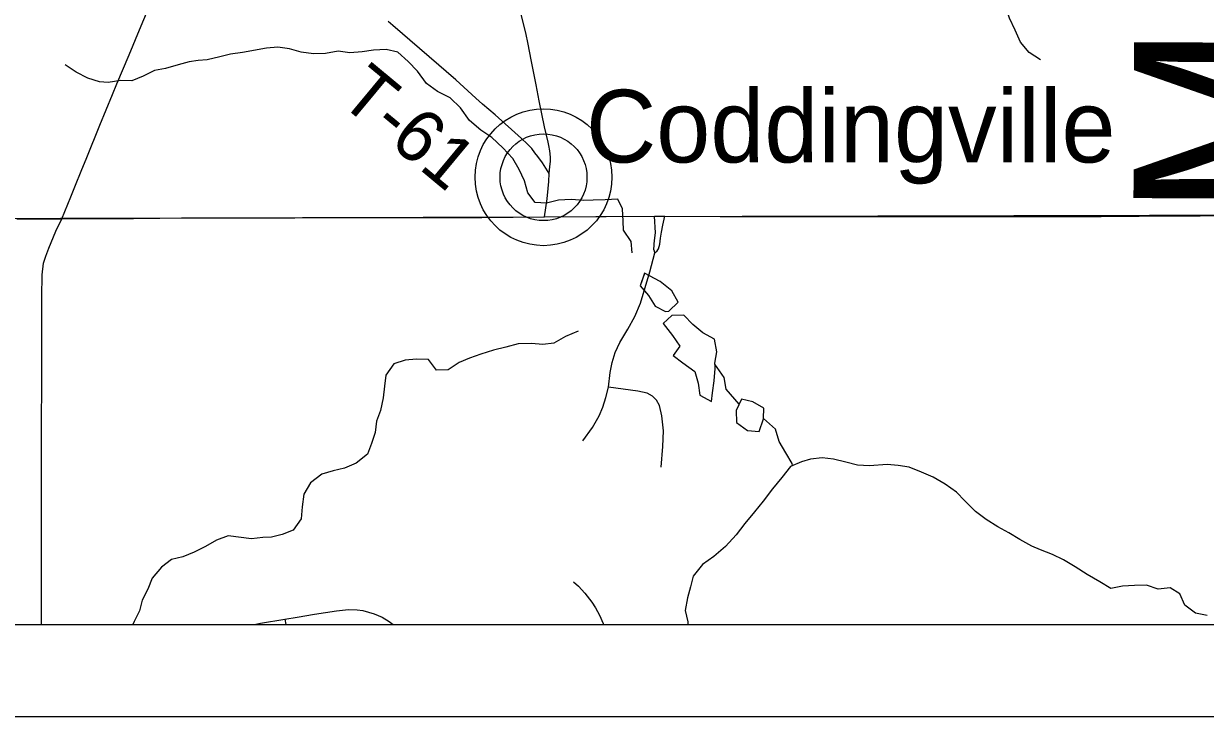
# Model space of a CAD drawing. Extents: x 0 to 34, y 0 to 22.
# Drawn here: x 6.454 to 7.738, y 14 to 14.753 of the extents above; entities that cross this region are included whole.
import ezdxf

# ---------------------------------------------------------------- set-up
doc = ezdxf.new("R2010")
doc.units = 0
for name, color, linetype in [('GM_X_Corporation', 7, 'Continuous'), ('GM_X_County_Text', 7, 'Continuous'), ('GM_X_Minor_Lake', 7, 'Continuous'), ('GM_X_Minor_River', 7, 'Continuous'), ('GM_X_State_Route', 7, 'Continuous'), ('GM_X_Township_Road', 7, 'Continuous'), ('GM_X_Township_Road_Text', 7, 'Continuous'), ('GM_X_Unincorporated', 7, 'Continuous'), ('GM_X_Unincorporated_Location', 7, 'Continuous'), ('GM_X_Unincorporated_Text', 7, 'Continuous'), ('SH_Data', 7, 'Continuous')]:
    doc.layers.add(name, color=color, linetype=linetype)

msp = doc.modelspace()

# ---------------------------------------------------------------- linework, layer by layer
at = {"layer": 'GM_X_Corporation'}
for points in [[(2.1, 20.9), (2.1, 14.1), (7.9734, 14.1), (7.9726, 14.5453), (7.9765, 15.2637), (7.9792, 15.5481), (7.979, 15.5988), (7.9808, 15.7192), (7.9807, 15.9078), (7.9821, 16.2487), (7.9825, 16.3395), (7.9818, 16.3982), (7.9825, 16.6077), (7.9838, 16.7968), (7.9877, 17.3871), (7.9891, 17.5498), (7.991, 17.7727), (7.9901, 18.1613)], [(7.9901, 18.1613), (7.991, 17.7727), (7.9891, 17.5498), (7.9877, 17.3871), (7.9838, 16.7968), (7.9825, 16.6077), (7.9818, 16.3982), (7.9825, 16.3395), (7.9821, 16.2487), (7.9807, 15.9078), (7.9808, 15.7192), (7.979, 15.5988), (7.9792, 15.5481), (7.9765, 15.2637), (7.9726, 14.5453), (7.0871, 14.5429), (7.0197, 14.5427), (6.4941, 14.5412), (6.1476, 14.5397), (5.4644, 14.5374), (4.5212, 14.531)]]:
    msp.add_lwpolyline(points, dxfattribs=at)
msp.add_lwpolyline([(2.8649, 14.1), (7.9734, 14.1), (7.9726, 14.5453), (7.0871, 14.5429), (7.0197, 14.5427), (6.4941, 14.5412), (6.1476, 14.5397), (5.4644, 14.5374), (4.5212, 14.531), (4.3772, 14.5296), (4.3422, 14.5307), (3.735, 14.5275), (3.3839, 14.5264), (3.3511, 14.525), (2.8655, 14.5214), (2.8638, 14.4461)], close=True, dxfattribs=at)
at = {"layer": 'GM_X_Minor_Lake'}
for points in [[(7.1289, 14.4817), (7.1239, 14.4682), (7.1331, 14.4576), (7.1404, 14.4458), (7.1514, 14.4402)], [(7.1288, 14.4816), (7.1239, 14.4682), (7.1331, 14.4576), (7.1404, 14.4458), (7.1514, 14.4402)], [(7.1514, 14.4402), (7.1552, 14.4406), (7.1654, 14.4502), (7.1585, 14.4627), (7.1459, 14.4729), (7.1289, 14.4817)], [(7.1514, 14.4402), (7.1552, 14.4406), (7.1654, 14.4502), (7.1585, 14.4627), (7.1459, 14.4729), (7.1289, 14.4817)], [(7.2054, 14.3815), (7.2053, 14.3839), (7.2072, 14.3964), (7.2049, 14.4101), (7.192, 14.4169), (7.1813, 14.4261), (7.1714, 14.4363), (7.1584, 14.4359), (7.1489, 14.4272), (7.1592, 14.4142)], [(7.1592, 14.4142), (7.1672, 14.4025), (7.16, 14.3922), (7.1703, 14.3842), (7.1833, 14.3751), (7.1871, 14.3622), (7.189, 14.3492), (7.2016, 14.3424), (7.2027, 14.3519), (7.2046, 14.3649), (7.2055, 14.3782), (7.2054, 14.3815)], [(7.1592, 14.4142), (7.1672, 14.4025), (7.16, 14.3922), (7.1703, 14.3842), (7.1833, 14.3751), (7.1871, 14.3622), (7.189, 14.3492), (7.2016, 14.3424), (7.2027, 14.3519), (7.2046, 14.3649), (7.2055, 14.3782), (7.2054, 14.3816)], [(7.2579, 14.3234), (7.2579, 14.3237), (7.2583, 14.3349), (7.2465, 14.3421), (7.2343, 14.3447), (7.2282, 14.3326)], [(7.2579, 14.3235), (7.2579, 14.3237), (7.2583, 14.3349), (7.2465, 14.3421), (7.2343, 14.3447), (7.2282, 14.3326)], [(7.2282, 14.3326), (7.2286, 14.3193), (7.2408, 14.3109), (7.2534, 14.3098), (7.2579, 14.3234)], [(7.2282, 14.3326), (7.2286, 14.3193), (7.2408, 14.3109), (7.2534, 14.3098), (7.2579, 14.3235)]]:
    msp.add_lwpolyline(points, dxfattribs=at)
at = {"layer": 'GM_X_Minor_River'}
for points in [[(7.5591, 14.7137), (7.5469, 14.7216), (7.5374, 14.733), (7.5316, 14.746), (7.5255, 14.7589), (7.5213, 14.7718), (7.5179, 14.7847), (7.5148, 14.798), (7.5121, 14.8102), (7.5053, 14.822), (7.5011, 14.8349), (7.4992, 14.8486), (7.4904, 14.8581), (7.4774, 14.8577)], [(7.1154, 14.5039), (7.1142, 14.5161), (7.1058, 14.5286), (7.1054, 14.5385), (7.105, 14.5518), (7.0997, 14.5621), (7.086, 14.5617), (7.073, 14.5613), (7.0628, 14.5609), (7.0491, 14.562), (7.0354, 14.5613), (7.0224, 14.5578), (7.0099, 14.5586), (7.0019, 14.5692), (6.9984, 14.5821), (6.9927, 14.5947), (6.9855, 14.6065), (6.9748, 14.6182), (6.963, 14.6292), (6.9508, 14.6372), (6.9386, 14.6479), (6.9287, 14.6615), (6.9176, 14.6725), (6.9039, 14.6794), (6.8917, 14.6881), (6.8822, 14.7014), (6.8719, 14.712), (6.8605, 14.7219), (6.8479, 14.7249), (6.8342, 14.7242), (6.8221, 14.7223), (6.8084, 14.7215), (6.7958, 14.723), (6.7821, 14.7207), (6.7692, 14.7203), (6.7555, 14.7222), (6.7429, 14.7256), (6.7304, 14.7275), (6.7178, 14.7263), (6.6919, 14.7217), (6.679, 14.7198), (6.6672, 14.7171), (6.6535, 14.7137), (6.6436, 14.7129), (6.6341, 14.7114), (6.622, 14.7083), (6.6083, 14.7045), (6.5961, 14.7022), (6.5839, 14.6961), (6.5718, 14.6908), (6.5596, 14.6911), (6.5459, 14.6892), (6.5364, 14.6899), (6.5238, 14.6937), (6.5112, 14.7002), (6.4991, 14.7082)], [(7.0565, 14.4187), (7.0428, 14.413), (7.0303, 14.4057), (7.0181, 14.4042), (7.0059, 14.4053), (6.9915, 14.4049), (6.9781, 14.4015), (6.9645, 14.398), (6.9508, 14.3938), (6.9386, 14.3896), (6.9272, 14.3847), (6.9154, 14.3767), (6.9028, 14.3763), (6.8941, 14.3881), (6.8811, 14.3884), (6.8686, 14.3873), (6.8564, 14.3834), (6.8477, 14.3709), (6.8462, 14.3591), (6.8447, 14.3462), (6.8417, 14.3325), (6.8375, 14.321), (6.836, 14.3085), (6.8322, 14.2967), (6.8276, 14.2849), (6.8155, 14.2754), (6.8029, 14.27), (6.7904, 14.267), (6.7782, 14.2632), (6.7657, 14.254), (6.7585, 14.2415), (6.7566, 14.2278), (6.7558, 14.2148), (6.7471, 14.2023), (6.7349, 14.1977), (6.7235, 14.195), (6.714, 14.1943), (6.7015, 14.1931), (6.6763, 14.1961), (6.6638, 14.1915), (6.6516, 14.1847), (6.6395, 14.1786), (6.6269, 14.1736), (6.6147, 14.1706), (6.6037, 14.1622), (6.5938, 14.1504), (6.5889, 14.1382), (6.5828, 14.1264), (6.5798, 14.1146), (6.5741, 14.1032), (6.5728, 14.1)], [(7.2315, 14.3393), (7.2175, 14.3557), (7.2152, 14.3683), (7.2053, 14.383)], [(7.2896, 14.2728), (7.2892, 14.2748), (7.2823, 14.2866), (7.2751, 14.2988), (7.2709, 14.3121), (7.2579, 14.3237)], [(7.7403, 14.1096), (7.7274, 14.1122), (7.7159, 14.121), (7.7106, 14.1331), (7.6999, 14.1396), (7.687, 14.1384), (7.6741, 14.1426), (7.6611, 14.1422), (7.6482, 14.1414), (7.6356, 14.1391), (7.6234, 14.1463), (7.6097, 14.1543), (7.5968, 14.1627), (7.5842, 14.1702), (7.572, 14.1759), (7.5591, 14.1809), (7.5496, 14.185), (7.5366, 14.1922), (7.5248, 14.1994), (7.5126, 14.2059), (7.5001, 14.2139), (7.4883, 14.2226), (7.4768, 14.2344), (7.4677, 14.2439), (7.4555, 14.2526), (7.4425, 14.2602), (7.4296, 14.2655), (7.4163, 14.2708), (7.4045, 14.2727), (7.3923, 14.2738), (7.3733, 14.2723), (7.3603, 14.273), (7.3474, 14.2764), (7.3341, 14.2795), (7.3219, 14.281), (7.309, 14.2798), (7.2995, 14.2767), (7.2873, 14.2718), (7.2778, 14.2596), (7.2679, 14.2474), (7.2577, 14.2341), (7.2482, 14.2223), (7.2379, 14.2097), (7.2284, 14.1972), (7.2166, 14.1846), (7.2041, 14.1739), (7.1919, 14.1652), (7.1817, 14.1526), (7.1787, 14.1408), (7.1753, 14.1287), (7.173, 14.115), (7.1757, 14.1028), (7.1759, 14.1)]]:
    msp.add_lwpolyline(points, dxfattribs=at)
at = {"layer": 'GM_X_State_Route'}
msp.add_line((7.1397, 14.5437), (7.1508, 14.5437), dxfattribs=at)
for points in [[(6.4465, 14.5409), (6.4708, 14.541), (6.4954, 14.541), (6.5324, 14.5412), (6.5735, 14.5414), (6.6019, 14.5415), (6.6619, 14.5418), (6.6991, 14.5419), (6.7489, 14.542), (6.9521, 14.5425), (7.02, 14.5429)], [(7.02, 14.5429), (7.0759, 14.5435), (7.1397, 14.5437)], [(7.1508, 14.5437), (7.2108, 14.5436), (7.591, 14.5434), (7.6249, 14.5436), (7.7079, 14.5441), (7.7327, 14.5443), (7.9738, 14.5455)]]:
    msp.add_lwpolyline(points, dxfattribs=at)
at = {"layer": 'GM_X_Township_Road'}
msp.add_line((6.738, 14.1055), (6.739, 14.1), dxfattribs=at)
for points in [[(6.4954, 14.541), (6.5052, 14.5647), (6.5104, 14.5775), (6.5166, 14.5927), (6.5226, 14.6075), (6.537, 14.6426), (6.5506, 14.6761), (6.5553, 14.6876), (6.5687, 14.7191), (6.5801, 14.7463), (6.5924, 14.7756), (6.6014, 14.7973), (6.6105, 14.8201), (6.63, 14.8663), (6.6397, 14.89), (6.6543, 14.9239)], [(7.0253, 14.5901), (7.0178, 14.6017), (7.0127, 14.6087), (7.0097, 14.6126), (7.0062, 14.6172), (7.0011, 14.6226), (6.9949, 14.6282), (6.9663, 14.6539), (6.9528, 14.6655), (6.9456, 14.6721), (6.9238, 14.6919), (6.8551, 14.7512), (6.8502, 14.7554)], [(7.0253, 14.5901), (7.026, 14.5979), (7.0264, 14.6031), (7.0267, 14.608), (7.0258, 14.6149), (7.0247, 14.6207), (7.0239, 14.6241), (7.0202, 14.6408), (7.0143, 14.6691), (7.0109, 14.6864), (7.0055, 14.7139), (7.0023, 14.7306), (6.9997, 14.7432), (6.9941, 14.7659)], [(7.02, 14.5429), (7.0229, 14.5628), (7.0241, 14.574), (7.0248, 14.5816), (7.0253, 14.5901)], [(6.4734, 14.1), (6.4735, 14.2437), (6.4736, 14.2803), (6.4734, 14.318), (6.4737, 14.3622), (6.4738, 14.4113), (6.474, 14.4562), (6.4742, 14.4799), (6.4757, 14.4927), (6.4781, 14.5004), (6.4813, 14.5089), (6.4889, 14.5276), (6.4954, 14.541)], [(7.1401, 14.5039), (7.1395, 14.5059), (7.139, 14.5076), (7.139, 14.5089), (7.1391, 14.5108), (7.1392, 14.5133), (7.1396, 14.5172), (7.1405, 14.5258), (7.1397, 14.5437)], [(7.1401, 14.5039), (7.1424, 14.506), (7.1438, 14.5082), (7.1448, 14.5107), (7.1453, 14.5132), (7.1462, 14.52), (7.1471, 14.5265), (7.1486, 14.5339), (7.1508, 14.5437)], [(7.0616, 14.2997), (7.0721, 14.3139), (7.0794, 14.3269), (7.0834, 14.3363), (7.0866, 14.3465), (7.0897, 14.3578), (7.0915, 14.374), (7.0936, 14.3848), (7.097, 14.3954), (7.1019, 14.4066), (7.1105, 14.421), (7.1183, 14.4347), (7.1243, 14.4492), (7.1347, 14.4834), (7.1401, 14.5039)], [(7.1467, 14.271), (7.1488, 14.2933), (7.1492, 14.3104), (7.1476, 14.3266), (7.145, 14.338), (7.1418, 14.3436), (7.1376, 14.348), (7.1316, 14.3513), (7.1216, 14.3535), (7.0897, 14.3578)], [(7.0514, 14.1462), (7.0569, 14.1416), (7.0639, 14.1339), (7.0714, 14.1242), (7.0756, 14.118), (7.0798, 14.1101), (7.0839, 14.1011), (7.0843, 14.1)], [(6.7044, 14.1), (6.7116, 14.1013), (6.738, 14.1055), (6.7513, 14.1077), (6.77, 14.111), (6.7942, 14.1147), (6.8071, 14.1163), (6.8165, 14.1159), (6.8227, 14.1152), (6.8348, 14.1115), (6.8437, 14.1079), (6.8514, 14.1032), (6.8556, 14.1)]]:
    msp.add_lwpolyline(points, dxfattribs=at)
at = {"layer": 'GM_X_Unincorporated'}
for radius in [0.0744, 0.0472]:
    msp.add_circle((7.019, 14.5861), radius, dxfattribs=at)
at = {"layer": 'GM_X_Unincorporated_Location'}
msp.add_line((7.019, 14.5861), (7.019, 14.5861), dxfattribs=at)
at = {"layer": 'SH_Data'}
for p, q in [((2.1, 14.1), (8.9, 14.1)), ((2, 14), (9, 14))]:
    msp.add_line(p, q, dxfattribs=at)

# ---------------------------------------------------------------- texts
at = {"layer": 'GM_X_County_Text'}
msp.add_text('MEDINA COUNTY', height=0.189394, rotation=89.8023, dxfattribs=at).set_placement((7.8494, 14.542))
at = {"layer": 'GM_X_Township_Road_Text'}
msp.add_text('T-61', height=0.05682, rotation=320.2854, dxfattribs=at).set_placement((6.7946, 14.6689))
at = {"layer": 'GM_X_Unincorporated_Text'}
msp.add_text('Coddingville', height=0.078977, rotation=0, dxfattribs=at).set_placement((7.0652, 14.6022))

doc.saveas('drawing.dxf')
